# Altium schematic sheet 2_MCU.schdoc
size 309 x 223 mm; Symbol: Artery_A4; Device: Artery_A4; Company: Artery Technology; Drawed: SD; Version: 1.3; Page Size: A4; @Project Name: AT-START-A403A V1.3; @Page Count: 5; @Update Date: 2023-11-22; @Create Date: 2022-12-01; @Schematic Name: AT_START_A403A; @Page No: 2; @Page Name: MCU
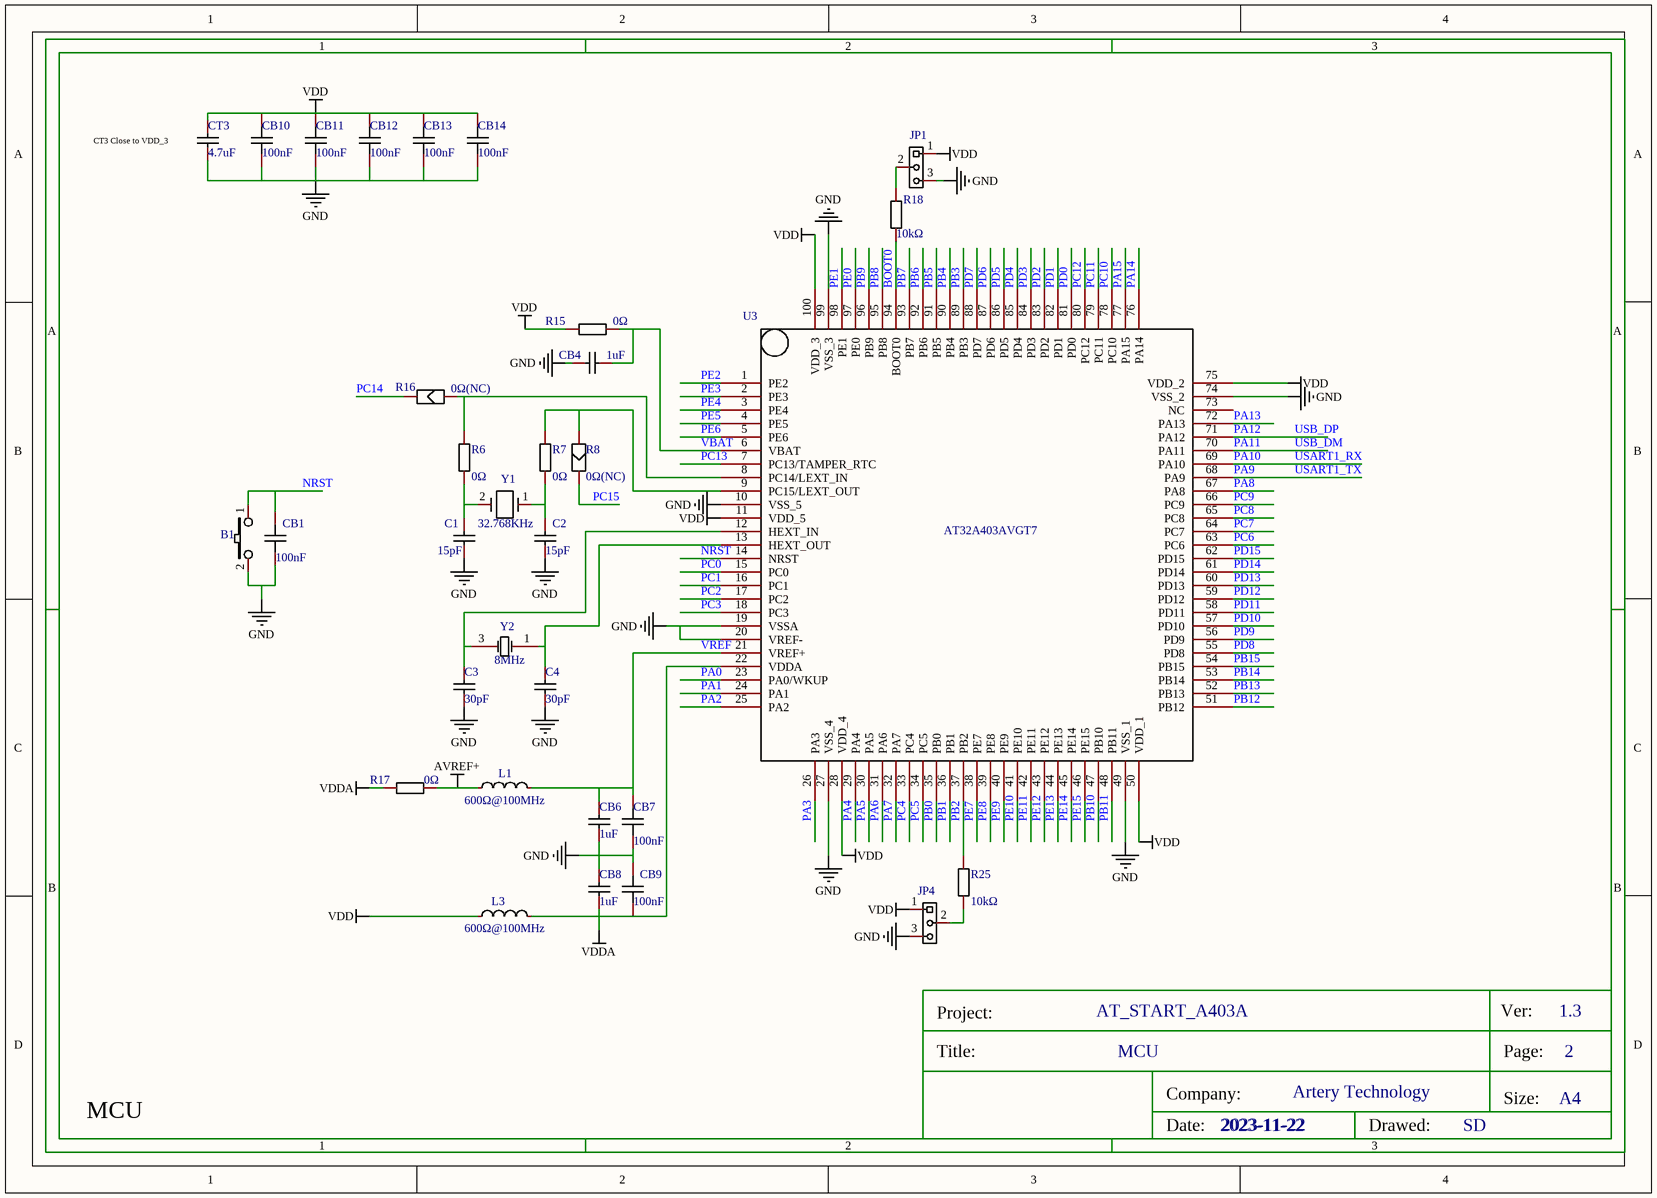
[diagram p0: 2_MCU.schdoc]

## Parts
B1  PB,BLACK,SMD_2P  [KEY_SOP_6*6]  (value not drawn)
C1  value 15pF  [C0603]  (hidden comment: CL10C150JB8NNNC)
C2  value 15pF  [C0603]  (hidden comment: CL10C150JB8NNNC)
C3  value 30pF  [C0603]  (hidden comment: 0603CG300J500NT)
C4  value 30pF  [C0603]  (hidden comment: 0603CG300J500NT)
CB1  value 100nF  [C0603]  (hidden comment: CC0603KRX7R9BB104)
CB4  value 1uF  [C0603]  (hidden comment: CL10A105KB8NNNC)
CB6  value 1uF  [C0603]  (hidden comment: CL10A105KB8NNNC)
CB7  value 100nF  [C0603]  (hidden comment: CC0603KRX7R9BB104)
CB8  value 1uF  [C0603]  (hidden comment: CL10A105KB8NNNC)
CB9  100nF  [C0603]
CB10  value 100nF  [C0603]  (hidden comment: CC0603KRX7R9BB104)
CB11  value 100nF  [C0603]  (hidden comment: CC0603KRX7R9BB104)
CB12  value 100nF  [C0603]  (hidden comment: CC0603KRX7R9BB104)
CB13  value 100nF  [C0603]  (hidden comment: CC0603KRX7R9BB104)
CB14  value 100nF  [C0603]  (hidden comment: CC0603KRX7R9BB104)
CT3  value 4.7uF  [C0603]  (hidden comment: CL10A475KO8NNNC)
JP1  1X3P_2.54M  [HDR1X3]  (value not drawn)
JP4  1X3P_2.54M  [HDR1X3]  (value not drawn)
L1  Impedance @ Frequency: 600Ω@100MHz  [L0603]  (hidden comment: GZ1608D601TF)
L3  Impedance @ Frequency: 600Ω@100MHz  [L0603]  (hidden comment: GZ1608D601TF)
R6  value 0Ω  [R0603]  (hidden comment: 0603WAF0000T5E)
R7  value 0Ω  [R0603]  (hidden comment: 0603WAF0000T5E)
R8  value 0Ω(NC)  [SB-PAD]  (hidden comment: NC)
R15  value 0Ω  [R0603]  (hidden comment: 0603WAF0000T5E)
R16  value 0Ω(NC)  [SB-PAD]  (hidden comment: NC)
R17  value 0Ω  [R0603]  (hidden comment: 0603WAF0000T5E)
R18  value 10kΩ  [R0603]  (hidden comment: 0603WAF1002T5E)
R25  value 10kΩ  [R0603]  (hidden comment: 0603WAF1002T5E)
U3  AT32A403AVGT7  [LQFP100_14*14]
Y1  32.768KHz  [XTAL_SOP - FC-12M]
Y2  8MHz  [SMD_5032_4P]

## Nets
AVREF+: L1.1 R17.1
GND: B1.2 C1.1 C2.1 C3.1 C4.1 CB1.1 CB4.1 CB6.1 CB7.1 CB8.2 CB9.2 CB10.1 CB11.1 CB12.1 CB13.1 CB14.1 CT3.1 JP1.3 JP4.3 U3.10(VSS_5) U3.19(VSSA) U3.20(VREF-) U3.27(VSS_4) U3.49(VSS_1) U3.74(VSS_2) U3.99(VSS_3)
VDD: CB10.2 CB11.2 CB12.2 CB13.2 CB14.2 CT3.2 JP1.1 JP4.1 L3.1 R15.1 U3.11(VDD_5) U3.28(VDD_4) U3.50(VDD_1) U3.75(VDD_2) U3.100(VDD_3)
VDDA: CB8.1 CB9.1 L3.2 R17.2 U3.22(VDDA)
BOOT0: R18.1 U3.94(BOOT0)
NRST: B1.1 CB1.2 U3.14(NRST)
PA0: U3.23(PA0/WKUP)
PA1: U3.24(PA1)
PA2: U3.25(PA2)
PA3: U3.26(PA3)
PA4: U3.29(PA4)
PA5: U3.30(PA5)
PA6: U3.31(PA6)
PA7: U3.32(PA7)
PA8: U3.67(PA8)
PA9: U3.68(PA9)  [also labelled USART1_TX]
PA10: U3.69(PA10)  [also labelled USART1_RX]
PA11: U3.70(PA11)  [also labelled USB_DM]
PA12: U3.71(PA12)  [also labelled USB_DP]
PA13: U3.72(PA13)
PA14: U3.76(PA14)
PA15: U3.77(PA15)
PB0: U3.35(PB0)
PB1: U3.36(PB1)
PB2: R25.2 U3.37(PB2)
PB3: U3.89(PB3)
PB4: U3.90(PB4)
PB5: U3.91(PB5)
PB6: U3.92(PB6)
PB7: U3.93(PB7)
PB8: U3.95(PB8)
PB9: U3.96(PB9)
PB10: U3.47(PB10)
PB11: U3.48(PB11)
PB12: U3.51(PB12)
PB13: U3.52(PB13)
PB14: U3.53(PB14)
PB15: U3.54(PB15)
PC0: U3.15(PC0)
PC1: U3.16(PC1)
PC2: U3.17(PC2)
PC3: U3.18(PC3)
PC4: U3.33(PC4)
PC5: U3.34(PC5)
PC6: U3.63(PC6)
PC7: U3.64(PC7)
PC8: U3.65(PC8)
PC9: U3.66(PC9)
PC10: U3.78(PC10)
PC11: U3.79(PC11)
PC12: U3.80(PC12)
PC13: U3.7(PC13/TAMPER_RTC)
PC14: R16.2
PC15: R8.2
PD0: U3.81(PD0)
PD1: U3.82(PD1)
PD2: U3.83(PD2)
PD3: U3.84(PD3)
PD4: U3.85(PD4)
PD5: U3.86(PD5)
PD6: U3.87(PD6)
PD7: U3.88(PD7)
PD8: U3.55(PD8)
PD9: U3.56(PD9)
PD10: U3.57(PD10)
PD11: U3.58(PD11)
PD12: U3.59(PD12)
PD13: U3.60(PD13)
PD14: U3.61(PD14)
PD15: U3.62(PD15)
PE0: U3.97(PE0)
PE1: U3.98(PE1)
PE2: U3.1(PE2)
PE3: U3.2(PE3)
PE4: U3.3(PE4)
PE5: U3.4(PE5)
PE6: U3.5(PE6)
PE7: U3.38(PE7)
PE8: U3.39(PE8)
PE9: U3.40(PE9)
PE10: U3.41(PE10)
PE11: U3.42(PE11)
PE12: U3.43(PE12)
PE13: U3.44(PE13)
PE14: U3.45(PE14)
PE15: U3.46(PE15)
VBAT: CB4.2 R15.2 U3.6(VBAT)
VREF: CB6.2 CB7.2 L1.2 U3.21(VREF+)
NetC1_2: C1.2 R6.1 Y1.2
NetC2_2: C2.2 R7.1 Y1.1
NetC3_2: C3.2 U3.12(HEXT_IN) Y2.3(OSC2)
NetC4_2: C4.2 U3.13(HEXT_OUT) Y2.1(OSC1)
NetJP1_2: JP1.2 R18.2
NetJP4_2: JP4.2 R25.1
NetR6_2: R6.2 R16.1 U3.8(PC14/LEXT_IN)
NetR7_2: R7.2 R8.1 U3.9(PC15/LEXT_OUT)

Not connected (* = marked no-connect by the designer): U3 73(NC)

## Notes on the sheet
- (near CT3) CT3 Close to VDD_3
- MCU
- 2023-11-22

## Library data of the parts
B1 = PB,BLACK,SMD_2P: Symbol: Push_Bottom,Blue,SMD_2P; Add into BOM: yes
C1 C2 = CL10C150JB8NNNC: 容值:15pF;精度:±5%;额定电压:50V;材质(温度系数):C0G;; Manufacturer: SAMSUNG(三星); Add into BOM: yes; Tolerance: ±5%; Voltage Rated: 50V; Temperature Coefficient: C0G
C3 C4 = 0603CG300J500NT: 容值:30pF;精度:±5%;额定电压:50V;材质(温度系数):C0G;; Manufacturer: FH(风华); Add into BOM: yes; Tolerance: ±5%; Voltage Rated: 50V; Temperature Coefficient: C0G
CB1 CB7 CB9-CB14 = CC0603KRX7R9BB104: 容值:100nF;精度:±10%;额定电压:50V;材质(温度系数):X7R;; Manufacturer: YAGEO(国巨); Add into BOM: yes; Tolerance: ±10%; Voltage Rated: 50V; Temperature Coefficient: X7R
CB4 CB6 CB8 = CL10A105KB8NNNC: 容值:1uF;精度:±10%;额定电压:50V;材质(温度系数):X5R;; Manufacturer: SAMSUNG(三星); Add into BOM: yes; Tolerance: ±10%; Voltage Rated: 50V; Temperature Coefficient: X5R
CT3 = CL10A475KO8NNNC: 容值:4.7uF;精度:±10%;额定电压:16V;材质(温度系数):X5R;; Manufacturer: SAMSUNG(三星); Add into BOM: yes; Tolerance: ±10%; Voltage Rated: 16V; Temperature Coefficient: X5R
JP1 JP4 = 1X3P_2.54M: Symbol: 1X3P,Male,DIP_2.54; Add into BOM: yes
L1 L3 = GZ1608D601TF: 标称阻抗@测试频率:600Ω@100MHz;误差:±25%;直流电阻(RDC):450mΩ;额定电流:200mA;电路数:1;; Manufacturer: Sunlord(顺络); Add into BOM: yes; Tolerance: ±25%; DC Resistance: 450mΩ; Current Rating: 200mA; Circuits: 1
R6 R7 R15 R17 = 0603WAF0000T5E: 电阻类型:厚膜电阻;阻值:0Ω;精度:±1%;功率:100mW;最大工作电压:75V;工作温度范围:-55℃~+155℃;; Manufacturer: UNI-ROYAL(厚声); Add into BOM: yes; Tolerance: ±1%; Power(Watts): 100mW; Overload Voltage (Max): 75V
R8 R16 = NC_SB-PAD: Convert to PCB: yes
R18 R25 = 0603WAF1002T5E: 电阻类型:厚膜电阻;阻值:10kΩ;精度:±1%;功率:100mW;温度系数:±100ppm/℃;最大工作电压:75V;工作温度范围:-55℃~+155℃;; Manufacturer: UNI-ROYAL(厚声); Add into BOM: yes; Tolerance: ±1%; Power(Watts): 100mW; Overload Voltage (Max): 75V
U3 = AT32F407VGT7: Symbol: LQFP100; Add into BOM: yes
Y1 = 32.768KHz: FC-12M 2012 EPSON; Symbol: 32.768KHz,CRY,30PPM,Size_3X8; Add into BOM: yes
Y2 = 8MHz: ?------; Symbol: SMD-5032_4P  8MHZ 20PF 10PPM; Add into BOM: yes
